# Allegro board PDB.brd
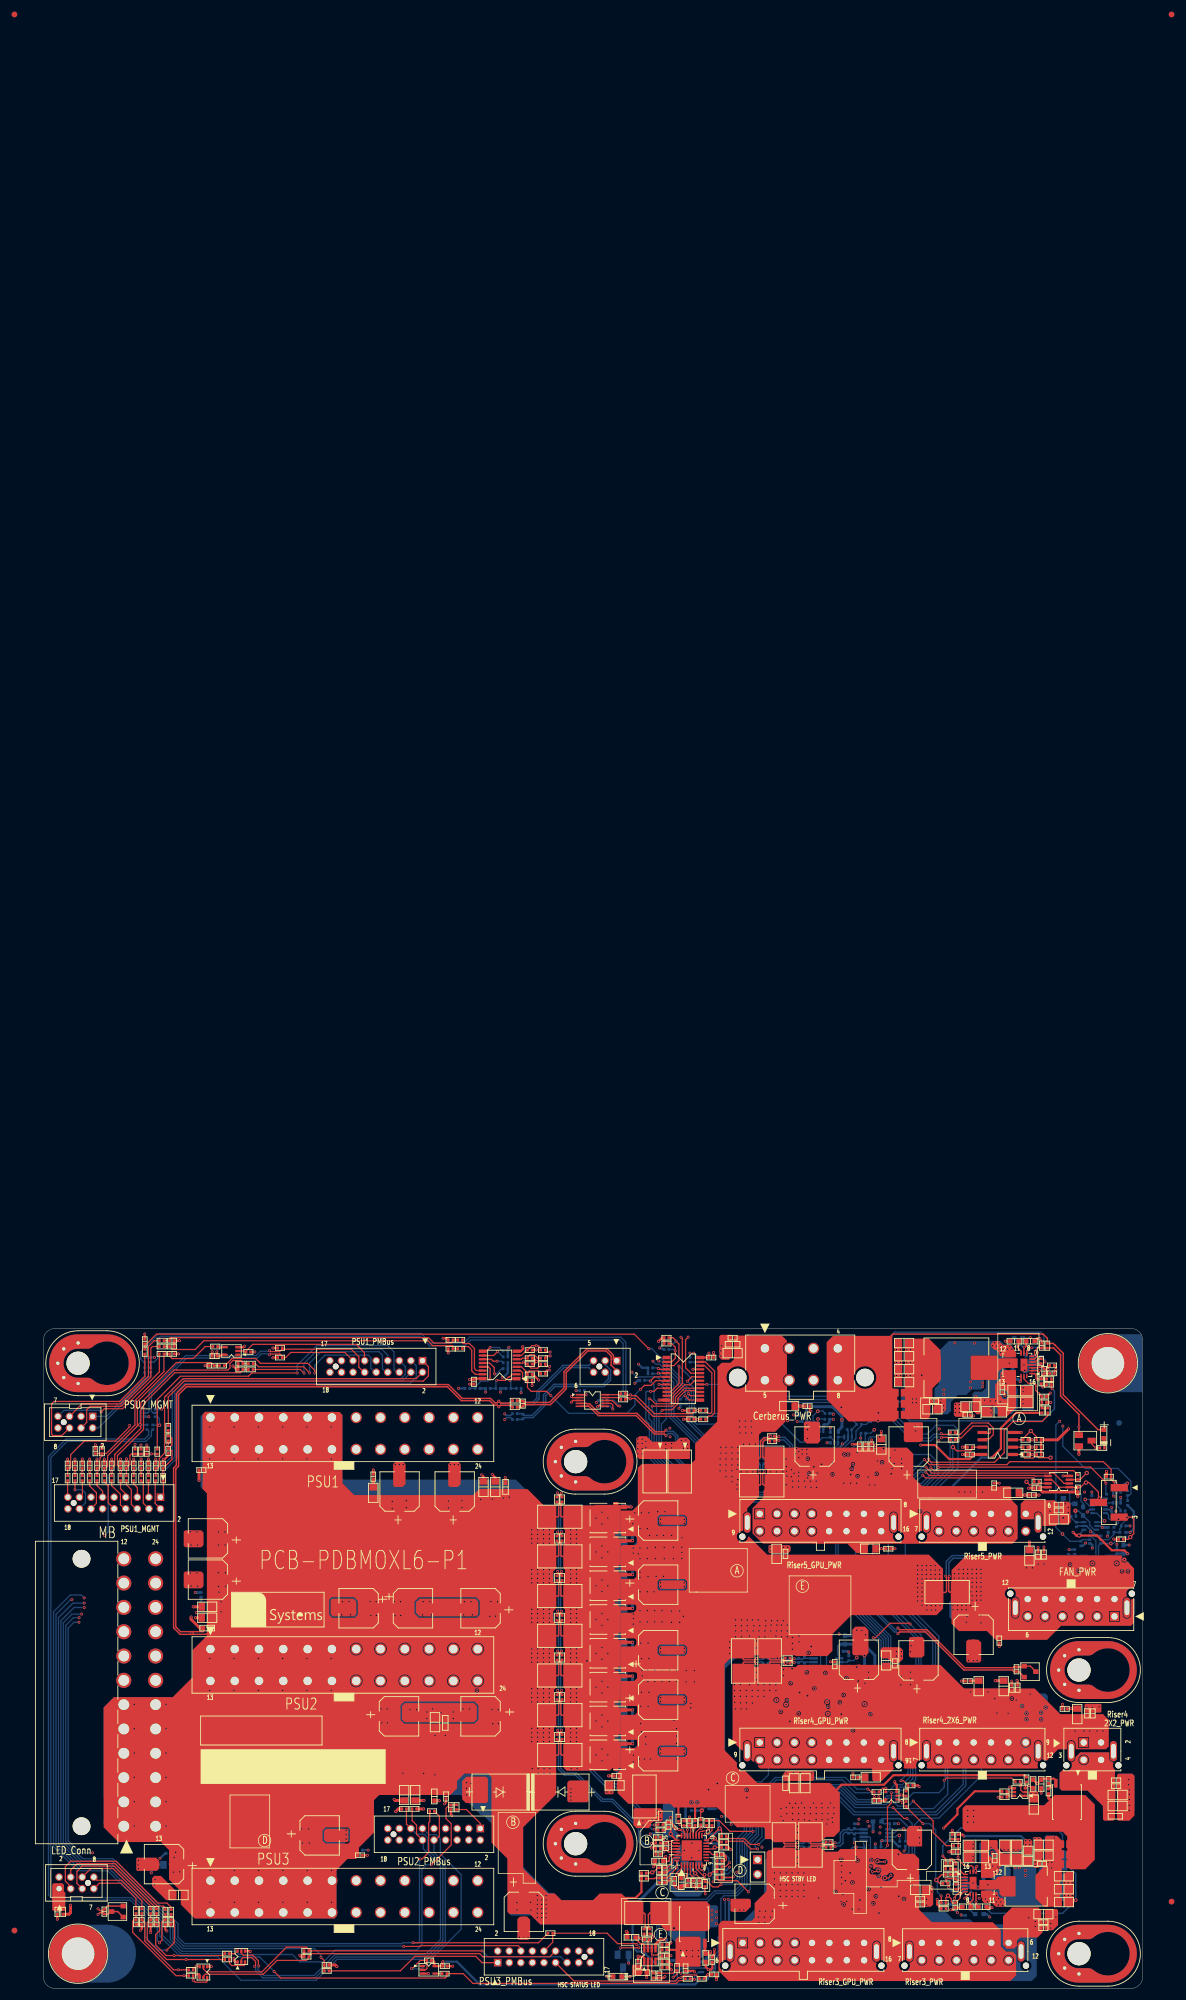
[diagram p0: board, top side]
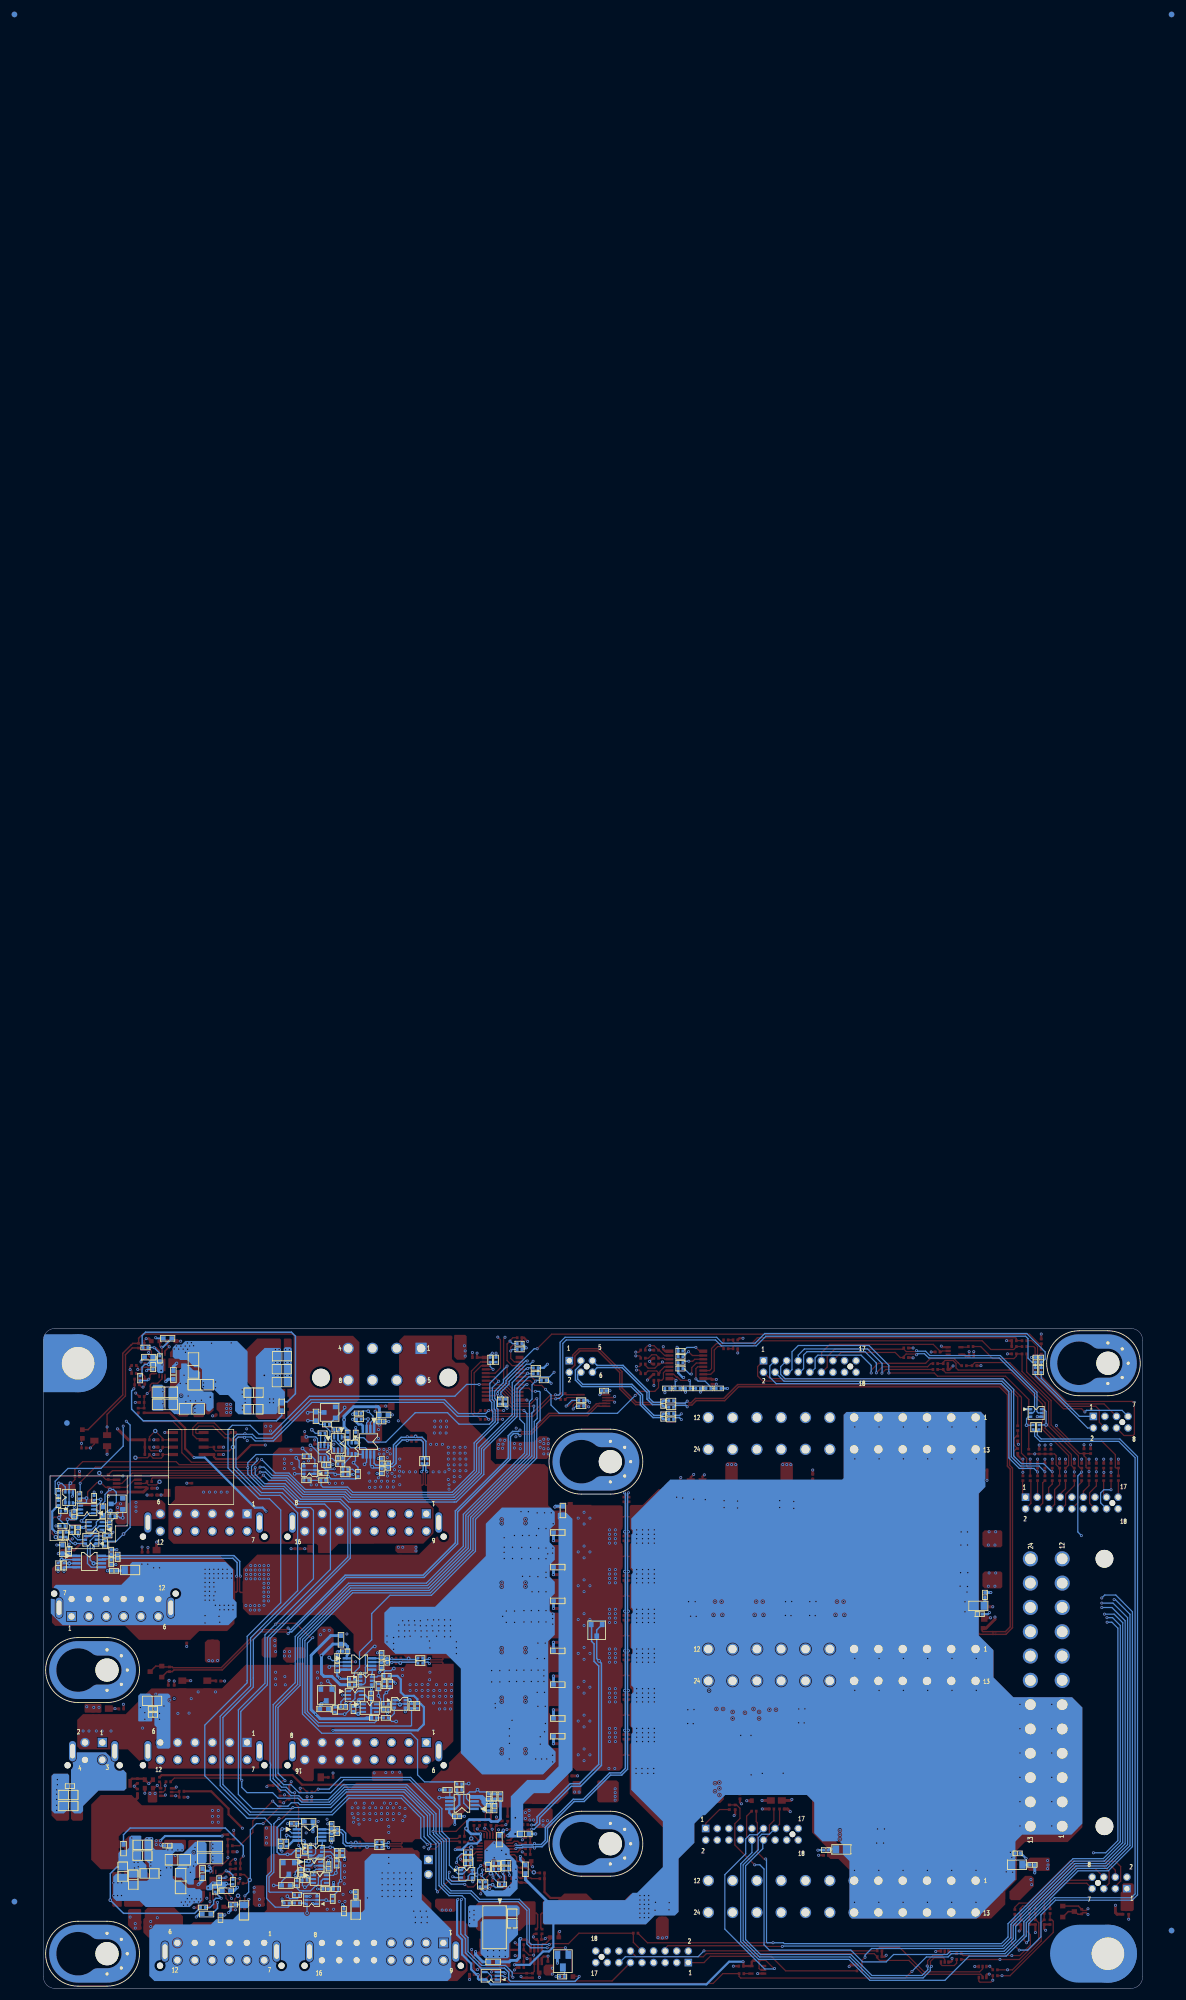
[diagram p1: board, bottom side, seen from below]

Outline 190 x 114 mm; copper layers: TOP, GND, VCC, VCC1, GND1, BOTTOM. Coordinates in mm from the lower left corner of the outline.
Outline path: 0,112 0,2 arc(0.59,0.59) 2,0 188,0 arc(189.41,0.59) 190,2 190,112 arc(189.93,112.52) 189.73,113 arc(189,113.73) 188,114 2,114 arc(0.59,113.41) 0,112

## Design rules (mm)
constraint set DEFAULT: min track width 0.216

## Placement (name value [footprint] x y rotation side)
C1  -  [EC_F80_H8]  61.57 85.84 90 top
C2  -  [EC_F80_H8]  71.09 85.84 90 top
C3  -  [EC_F80_H8]  20.85 21.48 180 top
C4  -  [EC_F80_H8]  83.06 13.22 270 top
C5  -  [C0805]  62.36 33.42 270 top
C6  -  [C0805]  76.07 86.63 90 top
C7  -  [C0805]  23.37 16.14 180 top
C8  -  [C0805]  28.32 64.02 180 top
C9  -  [C0805]  78.11 86.63 90 top
C10  -  [C0805]  67.69 45.99 90 top
C11  -  [C0805]  28.32 65.93 180 top
C12  -  [C0805]  64.26 33.42 270 top
C13  -  [C0603]  67.56 33.16 270 top
C14  -  [C0603]  69.47 45.86 90 top
C15  -  [C0603]  28.32 62.24 180 top
C16  -  [C0402]  144.02 32.4 180 top
C17  -  [C0603]  79.88 86.63 90 top
C18  -  [EC_F80_H8]  75.56 65.67 180 top
C19  -  [EC_F80_H8]  106.27 40.97 0 top
C20  -  [EC_F80_H8]  160.78 61.1 270 top
C21  -  [C0805]  131.7 35.45 90 top
C22  -  [C0805]  170.43 74.77 90 top
C23  -  [C0402]  99.06 36.72 180 top
C24  -  [C0402]  172.94 74.95 90 top
C25  -  [C0402]  17.53 111.77 90 top
C26  -  [C0402]  29.59 109.23 180 top
C27  -  [C0402]  17.88 92.73 90 top
C28  -  [C0402]  171.68 86.42 180 top
C29  -  [C0402]  29.08 107.58 180 top
C30  -  [C0402]  48.97 4.05 0 top
C31  -  [C0402]  70.42 31.3 270 top
C32  -  [C0402]  21.59 92.85 270 top
C33  -  [C0402]  74.42 104.79 270 top
C34  -  [C0402]  115.44 108.98 0 top
C35  -  [C0402]  93.09 103.27 180 bottom
C36  -  [C0402]  160.12 92.23 180 top
C37  -  [C0402]  168.2 55.13 270 top
C38  -  [C0402]  10.54 13.27 90 top
C39  -  [C0402]  131.55 57.57 90 bottom
C40  -  [C0402]  140.18 28.03 90 bottom
C41  -  [C0402]  131.55 55.79 270 bottom
C42  -  [C0402]  140.18 26.25 270 bottom
C43  -  [C0402]  146.69 28.46 180 bottom
C44  -  [C0402]  137.82 58.23 180 bottom
C45  -  [C0402]  149 25.01 270 bottom
C46  -  [C0402]  139.22 57.04 90 bottom
C47  -  [C0402]  145.47 20.06 270 bottom
C48  -  [C0402]  138.18 48.66 180 bottom
C49  -  [C0402]  131.5 91.12 90 bottom
C50  -  [C0402]  178.26 75.4 90 bottom
C51  -  [C0402]  131.5 89.35 270 bottom
C52  -  [C0402]  178.26 73.62 270 bottom
C53  -  [C0402]  131.57 97.93 0 bottom
C54  -  [C0402]  185.55 75.48 270 bottom
C55  -  [C0402]  135.48 99.33 0 bottom
C56  -  [C0402]  187.45 73.07 270 bottom
C57  -  [C0402]  139.32 96.53 180 bottom
C58  -  [C0402]  178.56 80.13 270 bottom
C59  -  [C0402]  113.03 33.16 270 bottom
C60  -  [C0402]  112.01 31.13 90 bottom
C61  -  [C0402]  118.49 29.73 180 bottom
C62  -  [C0402]  2.41 13.22 270 top
C63  -  [C0402]  128.27 75.07 90 top
C64  -  [C0402]  171.92 74.95 90 top
C65  -  [EC_F80_H8]  150.11 23.94 90 top
C66  -  [C0805]  151.54 17.03 0 top
C67  -  [C0402]  151.54 14.49 0 top
C68  -  [C0402]  151.54 15.51 0 top
C69  -  [EC_F80_H8]  133.3 93.61 90 top
C70  -  [C0805]  144.83 93.94 90 top
C71  -  [C0402]  142.11 93.61 90 top
C72  -  [EC_F80_H8]  151.26 56.66 90 top
C73  -  [C0402]  143.13 93.61 90 top
C74  -  [C0805]  145.67 56.66 90 top
C75  -  [C0402]  167.39 51.96 90 top
C76  -  [C0402]  147.19 56.15 90 top
C77  -  [EC_F80_H8]  61.47 47 0 top
C78  -  [EC_F80_H8]  28.45 70.63 180 top
C79  -  [EC_F80_H8]  47.75 26.43 0 top
C80  -  [EC_F80_H8]  75.56 47 180 top
C81  -  [EC_F80_H8]  28.45 77.74 180 top
C82  -  [EC_F80_H8]  63.88 65.67 0 top
C83  -  [EC_F80_H8]  54.48 65.67 180 top
C84  -  [EC_F80_H8]  122.94 14.62 180 top
C85  -  [C0402]  180.38 47.51 90 top
C86  -  [C0402]  181.39 47.51 90 top
C87  -  [EC_F80_H8]  149.56 93.61 90 top
C88  -  [C0805]  165.99 52.21 90 top
C89  -  [EC_F80_H8]  140.97 56.78 90 top
C90  -  [C0402]  185.42 34.94 0 bottom
C91  -  [C0402]  185.42 34.94 0 top
C92  -  [C0805]  185.67 33.42 0 bottom
C93  -  [C0402]  130.56 56.66 270 bottom
C94  -  [C0402]  139.19 27.19 270 bottom
C95  -  [C0402]  130.4 90.31 270 bottom
C96  -  [C0402]  177.16 74.56 270 bottom
C97  -  [C0402]  140.72 21.1 90 bottom
C98  -  [C0402]  133.35 50.56 90 bottom
C99  -  [C0402]  141.22 17.16 180 bottom
C100  -  [C0402]  130.81 48.15 180 bottom
C101  -  [C0402]  138.68 91.58 180 bottom
C102  -  [C0402]  184.02 79.24 270 bottom
C103  -  [C0402]  141.1 90.44 180 bottom
C104  -  [C0402]  184.66 81.9 270 bottom
C105  -  [C0402]  115.62 4.97 90 top
C106  -  [C0402]  102.79 4.26 270 top
C107  -  [C0402]  107.37 5.65 0 top
C108  -  [C0603]  101.65 8.83 180 top
C109  -  [C0402]  106.48 2.22 270 top
C110  -  [C0402]  104.32 8.45 0 top
C111  -  [C0402]  82.88 101.03 270 top
C112  -  [C0402]  82.88 98.8 90 bottom
C113  -  [C0402]  82.88 101.03 270 bottom
C114  -  [C0402]  69.39 3.85 0 top
C115  -  [C0402]  115.95 2.43 0 top
C116  -  [C0402]  8.99 92.8 90 top
C117  -  [C0805]  172.85 12.84 0 top
C118  -  [C0805]  171.2 49.67 0 bottom
C119  -  [C0402]  172.85 10.43 0 top
C120  -  [C0805]  175.51 81.04 0 top
C121  -  [C0402]  171.07 47.26 0 bottom
C122  -  [C0402]  172.85 11.44 0 top
C123  -  [C0402]  175.51 83.58 0 top
C124  -  [C0402]  171.07 48.27 0 bottom
C125  -  [C0402]  175.51 82.56 0 top
C126  -  [C0805]  108.97 12.08 90 bottom
C127  -  [C0402]  111 3.44 270 top
C128  -  [C0402]  4.19 90.29 90 top
C129  -  [C0402]  6.73 90.29 90 top
C130  -  [C0402]  9.27 90.29 90 top
C131  -  [C0402]  13.34 90.29 90 top
C132  -  [C0402]  15.62 90.29 90 top
C133  -  [C0402]  22.23 109.62 0 top
C134  -  [C0402]  18.16 90.29 90 top
C135  -  [C0402]  22.23 111.9 0 top
C136  -  [C0402]  20.7 90.29 90 top
C137  -  [C0402]  17.53 108.6 90 bottom
C138  -  [C0402]  5.46 90.29 90 top
C139  -  [C0402]  8 90.29 90 top
C140  -  [C0402]  22.23 110.89 0 top
C141  -  [C0402]  10.54 90.29 90 top
C142  -  [C0402]  18.54 108.6 90 bottom
C143  -  [C0402]  11.81 90.29 90 top
C144  -  [C0402]  14.35 90.29 90 top
C145  -  [C0402]  16.89 90.29 90 top
C146  -  [C0402]  19.43 90.29 90 top
C147  -  [C0402]  22.1 11.44 270 top
C148  -  [C0402]  19.56 11.44 270 top
C149  -  [C0402]  16 11.44 270 top
C150  -  [C0402]  17.02 11.44 270 top
C151  -  [C0402]  18.54 11.44 270 top
C152  -  [C0402]  21.08 11.44 270 top
C153  -  [C0402]  27.3 89.55 180 top
C154  -  [C0402]  21.62 23.33 180 bottom
C155  -  [C0402]  54.74 23 0 top
C156  -  [C0402]  28.17 64.66 180 bottom
C157  -  [C0402]  69.6 33.16 270 top
C158  -  [C0402]  119.13 112.41 180 top
C159  -  [C0402]  165.23 60.09 270 top
C160  -  [C0402]  159.38 12.21 90 bottom
C161  -  [C0402]  168.4 51.96 90 top
C162  -  [C0402]  164.34 86.88 90 top
C163  -  [C0402]  138.05 13.35 90 bottom
C164  -  [C0402]  136.78 56.02 90 top
C165  -  [C0402]  141.1 93.61 90 top
C166  -  [C0402]  57.02 88.41 90 top
C167  -  [C0402]  136.02 16.27 90 bottom
C168  -  [C0402]  19.05 21.35 180 bottom
C170  -  [C0402]  27.25 67.99 90 bottom
C171  -  [C0402]  140.34 36.46 180 top
C172  -  [C0402]  54.74 23.89 0 bottom
C174  -  [C0402]  177.8 72.15 0 bottom
C175  -  [C0402]  146.05 75.96 0 top
C176  -  [C0402]  132.08 100.6 0 top
C178  -  [C0402]  176.53 48.27 180 top
C191  -  [C0402]  157.23 14.49 0 bottom
C192  -  [C0402]  159.77 53.1 180 top
C193  -  [C0402]  170.81 85.23 0 top
CON1  -  [HEADER1X3S_P2-54H9-65XA]  184.15 83.96 0 top
D1  -  [LED0603]  99.21 2.05 0 top
D2  -  [SOT23]  147.57 20.72 270 bottom
D3  -  [SOT23]  141.1 50.69 270 bottom
D4  -  [SOT23]  140.51 99.51 0 bottom
D5  -  [SOT23]  177.29 83.71 0 bottom
D6  -  [LED0603]  183.26 95.77 270 top
D7  -  [POWERDI5_5-37X3-96]  105.66 89.3 270 top
D8  -  [POWERDI5_5-37X3-96]  112.01 10.56 270 bottom
D9  -  [POWERDI5_5-37X3-96]  109.98 89.3 270 top
D10  -  [POWERDI5_5-37X3-96]  103.89 33.16 90 top
D11  -  [D_SMCJ_6-85X5-9H2-62]  78.87 33.92 0 top
J1  -  [PWR2X12D_P4-2W5-5H12-8]  28.87 98.62 90 top
J2  -  [PWR2X12D2NH_P4-2W5-5H10_RA]  13.9 28.02 180 top
J3  -  [PWR2X12D_P4-2W5-5H12-8]  28.87 58.62 90 top
J4  -  [PWR2X12D_P4-2W5-5H12-8]  28.87 18.62 90 top
J5  -  [HEADER2X9D1NH_P2W2H6-4]  65.53 108.44 180 top
J6  -  [HEADER2X9D1NH_P2W2H6-4]  75.52 27.63 180 top
J7  -  [HEADER2X9D1NH_P2W2H6-4]  78.53 4.46 0 top
J8  -  [HEADER2X9D1NH_P2W2H6-4]  20.24 84.86 180 top
J9  -  [HEADER2X4D1NH_P2W2H6-4]  8.52 98.82 180 top
J10  -  [HEADER2X4D1NH_P2W2H6-4]  2.72 17.23 0 top
J11  -  [PWR2X6D2D2NH_P3W3H10-15]  185.13 64.26 270 top
J12  -  [PWR2X4D2NH_P4-2W5-5H12-8]  124.71 110.57 90 top
J13  -  [PWR2X8D2D2NH_P3W3H10-15]  120.86 7.86 90 top
J14  -  [PWR2X8D2D2NH_P3W3H10-15]  123.81 42.49 90 top
J15  -  [PWR2X8D2D2NH_P3W3H10-15]  123.81 81.98 90 top
J16  -  [PWR2X6D2D2NH_P3W3H10-15]  151.84 7.87 90 top
J17  -  [PWR2X6D2D2NH_P3W3H10-15]  154.79 42.49 90 top
J18  -  [PWR2X6D2D2NH_P3W3H10-15]  154.79 81.99 90 top
J19  -  [PWR2X2D2D2NH_P3W3H10-15]  179.81 42.49 90 top
J20  -  [HEADER1X2_P2-54H8-6]  123.44 22.24 0 top
J21  -  [HEADER2X3D1NH_P2W2H6-4]  99.1 108.44 180 top
L1  -  [B0402]  20.7 88.13 270 top
L2  -  [B0402]  18.16 88.13 270 top
L3  -  [B0402]  15.62 88.13 270 top
L4  -  [B0402]  13.34 88.13 270 top
L5  -  [B0402]  9.27 88.13 270 top
L6  -  [B0402]  6.73 88.13 270 top
L7  -  [B0402]  4.19 88.13 270 top
L8  -  [B0402]  17.53 106.82 270 bottom
L9  -  [B0402]  20.45 111.9 180 top
L10  -  [B0402]  20.45 109.62 180 top
L11  -  [B0402]  19.43 88.13 90 top
L12  -  [B0402]  16.89 88.13 90 top
L13  -  [B0402]  14.35 88.13 90 top
L14  -  [B0402]  11.81 88.13 90 top
L15  -  [B0402]  10.54 88.13 90 top
L16  -  [B0402]  8 88.13 90 top
L17  -  [B0402]  5.46 88.13 90 top
L18  -  [B0402]  18.54 106.82 90 bottom
L19  -  [B0402]  20.45 110.89 0 top
L20  -  [B0402]  17.53 110 90 top
L21  -  [B0402]  22.1 13.22 90 top
L22  -  [B0402]  19.56 13.35 90 top
L23  -  [B0402]  16 13.35 90 top
L24  -  [B0402]  21.08 13.22 270 top
L25  -  [B0402]  18.54 13.35 270 top
L26  -  [B0402]  17.02 13.35 270 top
L33  -  [B0402]  3.43 13.22 270 top
ME1  -  [ZT_LOG_6X16_Z1]  32.51 62.44 0 top
ME2  -  [LABEL20X4_SST21X5]  27.18 42.05 0 top
ME3  -  [LABEL_32X6_FULL]  27.18 35.32 0 top
MH1  -  [GND_C10D4_6-5B10_OB5]  6 108 90 top
MH2  -  [GND_C10D4_6-5B10_OB5]  92 25 90 top
MH3  -  [GND_C10D4_6-5B10_OB5]  92 91 90 top
MH4  -  [GND_C10D4_6-5B10_OB5]  179 55 90 top
MH5  -  [GND_C10D4_6-5B10_OB5]  179 6 90 top
MH6  -  [HOLE_C10D5-6B10_NPB_H11_STANDOFF]  184 108 0 top
MH7  -  [HOLE_C10D5-6B10_NPB_H11_STANDOFF]  6 6 0 top
NOREF  -  [unnamed]  195 341 0 top
NOREF#2  -  [unnamed]  195 15 0 top
NOREF#3  -  [unnamed]  -5 10 0 top
NOREF#4  -  [#2]  -20.95 -94.35 0 top
NOREF#5  -  [unnamed]  -5 341 0 top
NOREF#6  -  [unnamed]  -5 341 180 bottom
NOREF#7  -  [unnamed]  195 341 180 bottom
NOREF#8  -  [unnamed]  195 15 180 bottom
NOREF#9  -  [unnamed]  -5 10 180 bottom
NOREF#10  -  [unnamed]  185.93 97.68 180 bottom
PC28  -  [C0402]  173.74 35.83 90 top
PC29  -  [C0805]  171.2 31.76 90 top
PC30  -  [C0805]  185.67 31.51 0 top
PC31  -  [C0805]  185.67 31.51 0 bottom
PC32  -  [C0805]  185.67 33.42 0 top
PC33  -  [C0402]  185.42 35.96 0 top
PC34  -  [C0603]  172.47 35.32 270 top
PC101  -  [EC_F80_H8]  106.27 49.89 0 top
PC102  -  [EC_F80_H8]  106.27 58.42 0 top
PC103  -  [EC_F80_H8]  106.27 80.82 0 top
PC104  -  [C0805]  98.73 35.07 180 top
PC105  -  [C0805]  119.13 109.74 180 top
PC106  -  [EC_F80_H8]  106.27 69.75 0 top
PC107  -  [C0805]  126.75 75.07 90 top
PC108  -  [C0805]  129.79 35.45 90 top
PC109  -  [C0603]  110.26 18.35 270 top
PC819  -  [C0402]  157.7 23.61 180 top
PC820  -  [C0402]  157.62 14.37 270 top
PC822  -  [C0603]  162.34 14.11 0 top
PC823  -  [C0402]  159.61 18.66 270 bottom
PC824  -  [C0603]  159.57 14.11 180 top
PC825  -  [C0402]  164.42 22.51 90 top
PC827  -  [C1206]  161.17 22.63 180 top
PC828  -  [C0603]  162.48 19.95 270 bottom
PC829  -  [C0402]  157.71 19.28 90 top
PC830  -  [C1206]  161.17 24.7 180 top
PC831  -  [C0402]  156.34 19.67 0 top
PC832  -  [C1206]  166.2 23.45 90 top
PC833  -  [C1206]  168.26 23.45 90 top
PC834  -  [C0805]  176.29 20.18 270 bottom
PC835  -  [C0402]  172.61 21.55 180 top
PC836  -  [C1206]  166.28 18.55 270 bottom
PC837  -  [C0805]  176.41 14.92 0 top
PC838  -  [C0805]  176.4 19.39 0 top
PC840  -  [C0805]  174.46 18.79 270 bottom
PC841  -  [C0805]  172.88 24.8 180 top
PC842  -  [C0402]  156.35 21.62 180 top
PC843  -  [C1206]  161.17 22.44 180 bottom
PC844  -  [C0805]  172.86 24.8 180 bottom
PC845  -  [C0805]  176.4 17.15 0 top
PC846  -  [C1206]  166.76 22.23 0 bottom
PC847  -  [C0805]  171.65 19.87 180 bottom
PC848  -  [C0805]  172.88 22.95 180 top
PC849  -  [C1206]  161.2 24.52 180 bottom
PC850  -  [C0805]  172.87 22.95 180 bottom
PC851  -  [C0402]  168.56 24.67 180 bottom
PC1010  -  [C0402]  112.39 18.2 270 top
PC1011  -  [C0402]  116.84 23.13 0 top
PC1012  -  [C0402]  109.04 18.56 270 top
PC1013  -  [C0402]  107.39 18.68 270 top
PC1014  -  [C0402]  111.43 18.2 270 top
PC1015  -  [C0402]  107.39 20.44 270 top
PC1016  -  [C0402]  113.41 18.18 270 top
PC1017  -  [C0603]  106.43 21.99 180 top
PC1018  -  [C0402]  106.25 23.15 0 top
PC1019  -  [C0402]  107.62 24.63 90 top
PC1020  -  [C0402]  106.25 26.13 0 top
PC1021  -  [C0402]  108.05 28.28 270 top
PC1022  -  [C0603]  106.81 26.68 180 bottom
PC1023  -  [C0402]  111.68 28.54 90 top
PC1024  -  [C0603]  119.13 111.27 180 top
PC1819  -  [C0402]  172.97 102.25 0 top
PC1820  -  [C0402]  172.57 111.04 90 top
PC1822  -  [C0603]  167.84 111.81 180 top
PC1823  -  [C0402]  171.02 107.33 90 bottom
PC1824  -  [C0603]  170.61 111.81 0 top
PC1825  -  [C0402]  165.76 103.41 270 top
PC1827  -  [C1206]  168.88 103.28 0 top
PC1828  -  [C0603]  167.54 105.97 90 bottom
PC1829  -  [C0402]  172.99 106.64 270 top
PC1830  -  [C1206]  168.88 101.22 0 top
PC1831  -  [C0402]  174.35 106.25 180 top
PC1832  -  [C1206]  168.99 100.89 0 bottom
PC1833  -  [C1206]  169.01 102.97 0 bottom
PC1834  -  [C0805]  148.79 104.75 180 bottom
PC1835  -  [C0402]  153.94 101.45 0 top
PC1836  -  [C1206]  164.06 107.62 90 bottom
PC1837  -  [C0805]  148.77 109.22 180 top
PC1838  -  [C0805]  148.78 104.75 180 top
PC1840  -  [C0805]  148.78 106.99 180 top
PC1841  -  [C0805]  148.77 111.48 180 top
PC1842  -  [C0402]  173.83 104.29 0 top
PC1843  -  [C1206]  164.31 100.13 180 bottom
PC1844  -  [C0805]  148.77 109.22 180 bottom
PC1845  -  [C0805]  148.79 106.99 180 bottom
PC1846  -  [C1206]  164.31 99.62 180 top
PC1847  -  [C0805]  153.67 102.92 0 bottom
PC1848  -  [C0805]  153.67 100.05 0 top
PC1849  -  [C1206]  162.81 104.29 180 bottom
PC1850  -  [C0805]  153.68 100.05 0 bottom
PC1851  -  [C0402]  159.74 99.09 0 top
PD1  -  [D_SMCJ_6-85X5-9H2-62]  89.53 33.92 180 top
PL26  -  [IND_PCMC063T]  169.86 17.64 0 top
PL28  -  [B2012]  170.22 22.9 90 top
PL126  -  [IND_PCMB104TXA]  157.81 107.21 180 top
PL128  -  [B2012]  160.24 100.51 180 top
PQ2  -  [SOT363]  168.78 33.92 180 top
PQ3  -  [SOT1023]  176.91 32.02 270 top
PQ101  -  [DFN5_P1-27_4-9X5-9_Z1]  97.55 46.21 270 top
PQ102  -  [DFN5_P1-27_4-9X5-9_Z1]  97.55 40.36 270 top
PQ103  -  [DFN5_P1-27_4-9X5-9_Z1]  97.55 81.26 270 top
PQ104  -  [DFN5_P1-27_4-9X5-9_Z1]  97.55 69.57 270 top
PQ105  -  [DFN5_P1-27_4-9X5-9_Z1]  97.55 75.42 270 top
PQ106  -  [DFN5_P1-27_4-9X5-9_Z1]  97.55 63.73 270 top
PQ107  -  [DFN5_P1-27_4-9X5-9_Z1]  97.55 52.05 270 top
PQ108  -  [DFN5_P1-27_4-9X5-9_Z1]  97.55 57.89 270 top
PQ109  -  [SOT23]  94.36 61.86 270 bottom
PR22  -  [R0402]  168.4 35.7 0 top
PR23  -  [R0402]  166.12 34.05 0 top
PR24  -  [R0402]  166.12 33.03 180 top
PR25  -  [R0402]  169.93 36.08 270 top
PR26  -  [R0603]  171.07 35.32 90 top
PR27  -  [R0402]  173.74 34.05 90 top
PR101  -  [R0603]  101.09 66.94 180 bottom
PR102  -  [R0603]  101.09 46.62 180 bottom
PR103  -  [R0603]  101.09 43.58 180 bottom
PR104  -  [R0603]  100.2 82.56 270 bottom
PR105  -  [R0603]  101.09 72.79 180 bottom
PR106  -  [R0603]  101.09 78.75 180 bottom
PR107  -  [R0603]  101.09 58.31 180 bottom
PR108  -  [R0402]  110.72 17.97 0 bottom
PR109  -  [R0402]  113.13 21 90 bottom
PR702  -  [R0402]  157.73 24.65 0 top
PR704  -  [R0402]  155.6 14.79 0 top
PR705  -  [R0402]  155.6 13.78 0 top
PR706  -  [R0402]  157.72 17.55 90 top
PR707  -  [R0603]  158.4 16.87 180 bottom
PR708  -  [R0603]  161.8 12.84 180 bottom
PR710  -  [R0402]  155.91 18.15 180 top
PR711  -  [R0402]  160.31 17.08 270 bottom
PR712  -  [R0402]  157.25 18.4 90 bottom
PR714  -  [R0402]  162.43 13.98 0 bottom
PR716  -  [R0402]  157.71 21.03 90 top
PR717  -  [R0402]  156.35 20.66 180 top
PR719  -  [R0603]  176.15 24.14 270 bottom
PR1010  -  [R0402]  116.89 22.01 0 top
PR1011  -  [R0402]  116.89 21.05 180 top
PR1012  -  [R0402]  110.01 20.72 180 bottom
PR1013  -  [R0402]  110.01 21.71 0 bottom
PR1014  -  [R0402]  116.87 20.16 180 top
PR1015  -  [R0402]  88.77 64.02 270 top
PR1016  -  [R0402]  88.77 70.88 270 top
PR1017  -  [R0402]  88.77 77.74 270 top
PR1018  -  [R0402]  88.77 84.47 270 top
PR1019  -  [R0402]  88.77 57.16 270 top
PR1020  -  [R0402]  88.77 50.31 270 top
PR1027  -  [R0402]  89.66 50.31 270 top
PR1028  -  [R0402]  89.66 57.16 270 top
PR1029  -  [R0402]  89.66 64.02 270 top
PR1030  -  [R0402]  89.66 70.88 270 top
PR1031  -  [R0402]  89.66 77.74 270 top
PR1032  -  [R0402]  89.66 84.47 270 top
PR1033  -  [R0402]  106.43 18.68 270 top
PR1034  -  [R0402]  103.78 18.96 0 top
PR1035  -  [R0402]  111.76 20.61 0 bottom
PR1036  -  [R0402]  111.76 21.6 180 bottom
PR1037  -  [R0402]  106.43 20.44 270 top
PR1038  -  [R0402]  103.78 19.95 0 top
PR1039  -  [R0603]  106.68 20.59 90 bottom
PR1040  -  [R0603]  111.18 25.69 90 bottom
PR1041  -  [R0402]  106.25 24.14 0 top
PR1042  -  [R0402]  106.25 25.14 0 top
PR1043  -  [R0402]  117.63 26.28 0 top
PR1044  -  [R0402]  117.63 25.29 0 top
PR1045  -  [R0402]  112.65 28.56 270 top
PR1046  -  [R0402]  106.68 28.28 180 top
PR1047  -  [R0402]  106.68 27.32 180 top
PR1048  -  [R0402]  109.75 29.3 270 top
PR1049  -  [R0603]  101.09 52.47 180 bottom
PR1050  -  [R0402]  110.72 28.54 90 top
PR1705  -  [R0402]  173.53 111.03 270 top
PR1706  -  [R0402]  172.46 108.36 270 top
PR1707  -  [R0603]  171.78 109.04 0 bottom
PR1708  -  [R0603]  168.53 112.31 180 bottom
PR1710  -  [R0402]  174.34 107.62 0 top
PR1711  -  [R0402]  169.87 108.83 90 bottom
PR1712  -  [R0402]  173.28 105.4 270 bottom
PR1714  -  [R0402]  172.36 110.72 0 bottom
PR1716  -  [R0402]  172.48 104.88 270 top
PR1717  -  [R0402]  173.83 105.26 0 top
PR1719  -  [R0603]  148.79 100.56 90 bottom
PR10152  -  [R0402]  115.57 28.56 90 top
PR10153  -  [R0402]  117.63 24.32 180 top
PR10154  -  [R0402]  114.35 18.02 90 top
PSHORT5  -  [SHORT0805]  176.4 23.13 0 top
PSHORT6  -  [SHORT0805]  176.4 21.48 0 top
PSHORT7  -  [SHORT0805]  176.4 24.91 0 top
PSHORT15  -  [SHORT0805]  148.21 99.09 180 top
PSHORT61  -  [SHORT0805]  148.21 100.99 180 top
PSHORT71  -  [SHORT0805]  148.21 102.9 180 top
PU10  -  [R2512_SMD126X146]  132.59 24.78 270 top
PU11  -  [R2512_SMD126X146]  128.02 24.78 270 top
PU12  -  [LFCSP_WQ32_TH]  112.06 23.84 90 top
PU13  -  [R2512_SMD126X146]  120.95 56.57 270 top
PU14  -  [R2512_SMD126X146]  125.52 56.57 270 top
PU15  -  [R2512_SMD126X146]  124.17 91.66 0 top
PU16  -  [R2512_SMD126X146]  124.17 86.93 0 top
PU17  -  [R2512XA_Z1]  156.21 68.47 0 top
PU18  -  [R2512XA_Z1]  89.26 81.49 0 top
PU19  -  [R2512XA_Z1]  89.26 74.63 0 top
PU20  -  [R2512XA_Z1]  89.26 67.77 0 top
PU21  -  [R2512XA_Z1]  89.26 60.91 0 top
PU22  -  [R2512XA_Z1]  89.26 54.06 0 top
PU23  -  [R2512XA_Z1]  89.26 47.2 0 top
PU33  -  [PQFN17_IR3899]  161.84 18.2 270 top
PU113  -  [PQFN17_IR3899]  168.34 107.71 90 top
Q1  -  [SOT363]  144.02 89.55 0 bottom
Q2  -  [SOT363]  185.55 84.83 90 bottom
Q3  -  [SOT23_GDS]  100.2 4.71 270 bottom
Q4  -  [SOT23_GDS]  180.09 94.63 0 top
Q5  -  [SOT1023]  112.45 11.24 90 top
Q10  -  [SOT23]  170.54 54.73 0 top
Q11  -  [SOT23]  12.8 13.28 180 top
Q13  -  [SOT363]  142.85 23.61 180 bottom
Q14  -  [SOT363]  134.21 53.15 180 bottom
Q15  -  [SOT363]  136.7 93.31 270 bottom
Q16  -  [SOT363]  181.79 77.51 0 bottom
Q17  -  [SOT363]  143.64 15.25 0 bottom
Q18  -  [SOT363]  128.4 49.16 180 bottom
Q19  -  [SOT363]  116.81 19.8 180 bottom
Q20  -  [SOT363]  18.41 99.41 180 bottom
Q21  -  [SOT363]  34.21 5.5 90 top
Q22  -  [SOT363]  27.66 2.83 270 top
R1  -  [R0402]  144.53 87.77 0 bottom
R2  -  [R0402]  141.6 89.04 0 bottom
R3  -  [R0402]  187.4 85.56 90 bottom
R4  -  [R0402]  186.59 82.49 180 bottom
R5  -  [R0402]  144.48 91.91 0 bottom
R6  -  [R0402]  183.77 84.98 90 bottom
R7  -  [R0402]  147.96 14.75 180 bottom
R8  -  [R0402]  125.35 48.78 270 bottom
R9  -  [R0402]  141.6 87.77 0 bottom
R10  -  [R0402]  187.4 83.86 90 bottom
R11  -  [R0402]  113.59 17.97 90 bottom
R12  -  [R0402]  114.55 17.97 270 bottom
R13  -  [R0402]  116.87 19.17 0 top
R14  -  [R0402]  114.6 28.56 90 top
R15  -  [R0402]  173.61 99.84 90 top
R16  -  [R0402]  149.1 31.89 90 top
R17  -  [R0402]  144.78 24.02 90 bottom
R18  -  [R0402]  136.65 53.48 0 bottom
R19  -  [R0402]  136.02 95.65 90 bottom
R20  -  [R0402]  179.32 76.85 270 bottom
R21  -  [R0603]  144.15 28.84 180 bottom
R22  -  [R0603]  138.56 60.21 90 bottom
R23  -  [R0603]  131.19 99.07 180 bottom
R24  -  [R0603]  186.69 75.86 90 bottom
R25  -  [R0402]  132.84 46.75 180 bottom
R26  -  [R0402]  139.45 17.16 0 bottom
R27  -  [R0402]  130.05 52.59 90 bottom
R28  -  [R0402]  137.79 88.79 180 bottom
R29  -  [R0402]  186.69 79.9 0 bottom
R30  -  [R0402]  40.89 108.98 180 top
R31  -  [R0402]  62.36 31 180 top
R32  -  [R0402]  45.47 6.49 180 top
R33  -  [R0402]  40.89 110.63 180 top
R34  -  [R0402]  64.14 31 0 top
R35  -  [R0402]  45.47 5.48 180 top
R36  -  [R0402]  138.3 23.38 90 bottom
R37  -  [R0402]  130.68 53.99 0 bottom
R38  -  [R0402]  135.61 88.84 90 bottom
R39  -  [R0402]  187.07 78.37 270 bottom
R40  -  [R0603]  148.08 17.79 180 bottom
R41  -  [R0603]  141.48 48.27 180 bottom
R42  -  [R0603]  142.88 98.82 270 bottom
R43  -  [R0603]  179.71 82.44 270 bottom
R44  -  [R0402]  100.33 2.05 180 bottom
R45  -  [R0402]  183.01 93.36 0 top
R46  -  [R0402]  97.03 101.59 0 bottom
R47  -  [R0603]  103.56 2.73 0 top
R48  -  [R2512XA_Z1]  104.32 13.02 0 top
R49  -  [R0603]  112.27 4.59 0 bottom
R50  -  [R0603]  114.48 5.27 270 top
R51  -  [R0402]  35.84 106.92 0 top
R52  -  [R0402]  86.36 107.85 0 top
R53  -  [R0402]  86.36 110.27 0 top
R54  -  [R0402]  35.84 107.94 180 top
R55  -  [R0402]  86.36 106.2 180 top
R56  -  [R0402]  86.36 108.87 180 top
R57  -  [R0805]  178.69 47.39 90 top
R58  -  [R0402]  88.77 43.45 270 top
R59  -  [R0402]  184.15 88.41 0 top
R60  -  [R0402]  178.79 86.16 90 top
R61  -  [R0402]  186.26 77.59 180 top
R62  -  [R0402]  35.43 109.95 180 top
R63  -  [R0402]  66.67 4.84 180 top
R64  -  [R0402]  113.79 1.67 180 top
R65  -  [R0402]  19.68 92.72 270 top
R66  -  [R0402]  15.85 92.73 270 top
R67  -  [R0402]  16.86 92.73 270 top
R68  -  [R0402]  29.72 110.89 180 top
R69  -  [R0402]  30.86 107.58 0 top
R70  -  [R0402]  67.18 30.62 0 top
R71  -  [R0402]  87.63 9.54 0 top
R72  -  [R0402]  21.59 96.79 270 top
R73  -  [R0402]  71.44 31.3 90 top
R74  -  [R0402]  48.97 3.04 180 top
R75  -  [R0402]  171.68 87.56 180 top
R76  -  [R0402]  178.79 88.32 90 top
R77  -  [R0402]  73.28 103.65 0 bottom
R78  -  [R0402]  75.06 103.65 0 bottom
R79  -  [R0402]  107.7 111.39 0 bottom
R80  -  [R0402]  107.7 112.41 180 top
R81  -  [R0402]  78.61 103.65 180 bottom
R82  -  [R0402]  76.83 103.65 180 bottom
R83  -  [R0402]  107.7 110.38 0 bottom
R84  -  [R0402]  107.7 111.39 180 top
R85  -  [R0402]  80.39 103.65 0 bottom
R86  -  [R0402]  82.17 103.65 0 bottom
R87  -  [R0402]  112.78 108.6 270 bottom
R88  -  [R0402]  111.76 108.6 90 bottom
R89  -  [R0402]  72.03 110.5 0 top
R90  -  [R0402]  72.03 112.03 0 top
R91  -  [R0402]  114.05 98.31 0 top
R92  -  [R0402]  114.05 99.84 0 top
R93  -  [R0402]  84.07 106.07 180 top
R94  -  [R0402]  84.07 107.85 180 top
R95  -  [R0402]  84.07 108.87 180 top
R96  -  [R0402]  84.07 110.27 180 top
R97  -  [R0402]  79.88 110.12 180 bottom
R98  -  [R0402]  79.88 109.11 180 bottom
R99  -  [R0402]  79.88 108.09 180 bottom
R100  -  [R0402]  79.88 107.08 180 bottom
R101  -  [R0402]  34.06 107.94 0 top
R102  -  [R0402]  34.06 106.92 0 top
R103  -  [R0402]  70.38 110.5 0 top
R104  -  [R0402]  70.38 112.03 0 top
R105  -  [R0402]  112.01 98.31 0 top
R106  -  [R0402]  112.01 99.84 0 top
R107  -  [R0402]  104.9 107.2 0 bottom
R108  -  [R0402]  104.9 106.19 0 bottom
R109  -  [R0402]  84.07 105.06 180 top
R110  -  [R0402]  21.59 95.01 90 top
R111  -  [R0402]  110.11 101.36 90 bottom
R112  -  [R0402]  111.12 101.36 90 bottom
R113  -  [R0402]  157.2 96.04 0 top
R114  -  [R0402]  157.2 94.77 0 top
R115  -  [R0402]  100.2 102.76 180 top
R116  -  [R0402]  100.2 101.74 180 top
R117  -  [R0402]  160.12 93.5 180 top
R118  -  [R0402]  172.06 92.23 180 top
R119  -  [R0402]  169.77 92.23 0 top
R120  -  [R0402]  172.06 93.5 180 top
R121  -  [R0402]  169.77 93.5 0 top
R122  -  [R0402]  172.06 94.77 180 top
R123  -  [R0402]  169.77 94.77 0 top
R124  -  [R0402]  97.03 100.57 0 bottom
R125  -  [R0603]  128.27 35.45 90 top
R126  -  [R0402]  145.92 23.38 270 bottom
R127  -  [R0402]  148.01 24.98 270 bottom
R128  -  [R0402]  136.65 52.47 180 bottom
R129  -  [R0402]  139.22 55.31 270 bottom
R130  -  [R0402]  139.32 23.38 270 bottom
R131  -  [R0402]  131.06 52.59 270 bottom
R132  -  [R0402]  139.32 21.6 270 bottom
R133  -  [R0402]  132.08 52.21 270 bottom
R134  -  [R0402]  146.18 18.18 90 bottom
R135  -  [R0402]  139.57 48.15 90 bottom
R136  -  [R0402]  144.83 18.68 180 bottom
R137  -  [R0402]  136.4 48.27 90 bottom
R138  -  [R0603]  185.29 29.73 0 top
R139  -  [R0402]  89.66 43.45 270 top
R140  -  [R0402]  137.41 95.65 270 bottom
R141  -  [R0402]  135.48 98.31 0 bottom
R142  -  [R0402]  178.94 78.25 0 bottom
R143  -  [R0402]  186.44 73.07 270 bottom
R144  -  [R0402]  137.79 89.68 0 bottom
R145  -  [R0402]  186.06 78.37 90 bottom
R146  -  [R0402]  138.68 90.57 0 bottom
R147  -  [R0402]  185.04 79.24 90 bottom
R148  -  [R0402]  140.97 97.42 180 bottom
R149  -  [R0402]  178.05 81.55 180 bottom
R150  -  [R0402]  141.73 95.9 180 bottom
R151  -  [R0402]  181.23 84.72 90 bottom
R152  -  [R0402]  107.37 4.64 180 top
R153  -  [R0402]  107.37 3.62 0 top
R154  -  [R0402]  103.81 9.84 270 top
R155  -  [R0402]  104.83 9.84 270 top
R156  -  [R0402]  120.14 34.3 0 bottom
R157  -  [R0402]  116.59 23.51 180 bottom
R158  -  [R0402]  116.59 22.62 0 bottom
R159  -  [R0402]  146.18 14.75 180 bottom
R160  -  [R0402]  140 15.48 270 bottom
R161  -  [R0402]  126.36 48.78 90 bottom
R162  -  [R0402]  130.81 49.16 180 bottom
R163  -  [R0402]  116.59 21.6 0 bottom
R164  -  [R0402]  113.61 28.69 90 top
R165  -  [R0402]  111 33.16 90 bottom
R166  -  [R0402]  112.01 33.16 270 bottom
R167  -  [R0402]  113.03 31.13 90 bottom
R168  -  [R0402]  118.11 34.3 180 bottom
R169  -  [R0402]  118.11 35.32 0 bottom
R170  -  [R0402]  146.18 16.14 0 bottom
R171  -  [R0402]  109.52 3.49 270 top
R172  -  [R0402]  130.81 46.75 0 bottom
R173  -  [R0402]  105.46 2.22 270 top
R174  -  [R0402]  17.91 96.95 90 bottom
R175  -  [R0402]  31.75 6.01 0 top
R176  -  [R0402]  25.5 2.2 0 top
R177  -  [R0402]  18.92 96.95 270 bottom
R178  -  [R0402]  31.75 5 180 top
R179  -  [R0402]  25.5 3.22 180 top
R180  -  [R0402]  107.37 6.67 180 top
R181  -  [R0402]  107.37 7.56 0 top
R182  -  [R0402]  135.7 25.27 180 top
R183  -  [R0402]  149.1 33.67 270 top
R184  -  [R0402]  144.02 33.92 180 top
R185  -  [R0402]  103.5 105.04 0 bottom
R186  -  [R0402]  69.34 2.55 0 top
R187  -  [R0402]  111.38 1.67 180 top
R188  -  [R0402]  10.13 92.8 270 top
R189  -  [R2512XA_Z1]  89.26 40.34 0 top
R191  -  [R0402]  81.48 101.54 180 top
R192  -  [R0402]  81.48 100.4 180 top
R193  -  [R0402]  81.48 98.29 180 bottom
R194  -  [R0402]  81.48 99.3 180 bottom
R195  -  [R0402]  81.48 101.54 180 bottom
R196  -  [R0402]  81.48 100.4 180 bottom
R197  -  [R0402]  172.97 101.23 0 top
R198  -  [R0402]  172.59 99.84 90 top
R199  -  [R0402]  157.1 26.18 90 top
R200  -  [R0402]  158.12 26.18 270 top
R201  -  [R0402]  131.91 25.28 180 bottom
R202  -  [R0402]  124.85 57.07 180 bottom
R203  -  [R0402]  128.63 57.06 180 top
R204  -  [R0402]  135.7 24.38 0 top
R205  -  [R0402]  131.91 24.39 0 bottom
R206  -  [R0402]  124.85 56.18 0 bottom
R207  -  [R0402]  128.63 56.17 0 top
R208  -  [R0402]  123.67 91.08 270 bottom
R209  -  [R0402]  125.97 95.41 180 top
R210  -  [R0402]  124.56 91.08 90 bottom
R211  -  [R0402]  125.97 94.52 0 top
R212  -  [R0402]  149.86 35.07 0 top
R221  -  [R0805]  155.32 13.48 90 bottom
R222  -  [R0805]  161.67 52.21 90 top
R223  -  [R0805]  167.64 85.61 0 top
R234  -  [R0805]  57.02 85.61 90 top
R235  -  [R0805]  136.02 13.6 90 bottom
R236  -  [R0805]  21.72 21.35 180 bottom
R238  -  [R0805]  28.4 66.08 180 bottom
R239  -  [R0805]  143 36.46 180 top
R240  -  [R0805]  52.07 24.02 0 bottom
R242  -  [R0805]  175.01 72.28 0 bottom
R243  -  [R0805]  142.88 75.96 0 top
R244  -  [R0805]  128.91 100.6 0 top
SHORT1  -  [SHORT10X30_M]  25.64 61.17 0 top
SHORT2  -  [SHORT10X30_M]  25.64 61.62 0 top
U1  -  [TSSOP24_P0-65W5-85H1-1_Z1]  110.62 105.31 0 top
U2  -  [MSOP10_P0-5W4-4_3X3]  94.91 101.56 0 top
U3  -  [SOIC8]  164.95 94.14 180 top
U4  -  [SC70-6XB]  143.18 21.22 180 bottom
U5  -  [SC70-6XB]  142.19 18.89 180 bottom
U6  -  [SC70-6XB]  136.14 50.69 180 bottom
U7  -  [SC70-6XB]  133.55 48.43 180 bottom
U8  -  [SC70-6XB]  139.09 94.15 270 bottom
U9  -  [SC70-6XB]  141.43 92.65 270 bottom
U10  -  [SC70-6XB]  180.95 79.9 0 bottom
U11  -  [SC70-6XB]  182.45 82.74 0 bottom
U12  -  [SC70-5XA]  146.56 33.29 180 top
U13  -  [TSSOP8_P0-65W3-7H1-1]  175.49 87.56 180 top
U14  -  [TSSOP16_P0-65W5-85H1-1XB]  78.87 107.71 180 top
U15  -  [VSSOP8]  143.99 26.51 180 bottom
U16  -  [VSSOP8]  135.36 56.05 180 bottom
U17  -  [VSSOP8]  133.81 94.45 270 bottom
U18  -  [VSSOP8]  182.07 73.75 180 bottom
U19  -  [VSSOP8]  117.65 31.99 0 bottom
U20  -  [TSOT8]  104.83 5.78 90 top
U21  -  [SC70-5XB]  32.51 110.12 180 top
U22  -  [SC70-5XB]  66.6 3.22 0 top
U23  -  [SC70-5XB]  112.65 2.17 0 bottom

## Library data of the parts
C1-C4 C18-C20 C65 C69 C72 C77-C84 C87 C89 PC101-PC103 PC106 = CAPP: part number: CAPP_-270UF,CAP-PLE00270-E0,POLCAP,20%,16V
C5-C8 C21 C22 C66 C70 C74 C88 C92 C117 C118 C120 C126 = CAP: part number: CAP_0805-10UF,CAP-85E00010-D0,X6S,10%,16V
C9-C12 = CAP: part number: CAP_0805-0.1UF,CAP-85G000D1-C0,X7R,5%,50V
C13-C15 C17 = CAP: part number: CAP_0603-1000PF,CAP-63G0D001-C0,X7R,5%,50V
C16 C23 C24 C26-C36 C61 C62 C67 C71 C75 C86 C91 C97-C104 C107 C109 C114 C115 C119 C121 C123 C127 PC28 PC33 PC835 PC851 PC1011 PC1835 PC1851 = CAP: part number: CAP_0402-0.1UF,CAP-42E000D1-D0,X7R,10%,16V
C25 C128-C152 C166-C168 C170-C172 C174-C176 C178 C191-C193 PC823 PC1823 = CAP: part number: CAP_0402-100PF,CAP-42GD0001-C0,NP0,5%,50V
C37 C38 PC842 PC1842 = CAP: part number: CAP_0402-2200PF,CAP-42GD0022-D0,X7R,10%,50V
C39-C42 C49-C52 = CAP: part number: CAP_0402-100PF,CAP-42GD0001-C0,EMPTY,5%,50V
C43 C44 C53 C54 C59 C60 PC825 PC1825 = CAP: part number: CAP_0402-0.1UF,CAP-42F000D1-D0,X7R,10%,25V
C45 C46 C55 C56 C63 C64 C68 C73 C76 C85 C90 C93-C96 C105 C111-C113 C122 C124 C125 PC819 PC1016 PC1021 PC1819 = CAP: part number: CAP_0402-1000PF,CAP-42G0D001-D0,X7R,10%,50V
C47 C48 C57 C58 = CAP: part number: CAP_0402-1UF,CAP-42C00001-D0,X7R,10%,6.3V
C106 = CAP: part number: CAP_0402-0.015UF,CAP-42E0D015-D0,X7R,10%,16V
C108 PC828 PC1024 PC1828 = CAP: part number: CAP_0603-0.1UF,CAP-63G000D1-D0,X7R,10%,50V
C110 PC820 PC1820 = CAP: part number: CAP_0402-1000PF,CAP-42G0D001-D0,EMPTY,10%,50V
C116 = CAP: part number: CAP_0402-0.1UF,CAP-42E000D1-D0,EMPTY,10%,16V
C153-C165 = CAP: part number: CAP_0402-33PF,CAP-42G0033P-C0,NP0,5%,50V
CON1 = HEADER1X3: part number: HEADER1X3_-HEADER1X3S,COH-003SM254-02,IO,,,
D1 D6 = LED_2P: part number: LED_2P_-LTST-C193KGKT-5A,LED-S1SG000V-00,IC,,
D2-D5 = BAT54_7_F: part number: BAT54_7_F_-BAT54-7-F,DOD-DSBAT547-00,IC,,,
D7-D10 = SCHOTTKY_BARRIER_RECTIFIER_3S: part number: SCHOTTKY_BARRIER_RECTIFIER_3S_-PDS1040-13,DOD-DSPDS104-00,IC,,
D11 PD1 = TVS_DIODE: part number: TVS_DIODE_-5.0SMDJ15A,DOD-LF50SMDJ-00,IC,,,
J1 J3 J4 = PWR2X12: part number: PWR2X12_-PWR2X12,COP-024D4D20-00,IO,,
J2 = PWR2X12: part number: PWR2X12_-RA_2NH_PWR2X12,COP-024D4D20-03,IO,,
J5-J8 = HEADER2X9Z: part number: HEADER2X9Z_-1NH_HEADER2X9,COH-018DM200-00,IO,,
J9 J10 = HEADER2X4Z: part number: HEADER2X4Z_-1NH_HEADER2X4,COH-008DM002-02,IO,,
J11 J16-J18 = PWR2X6_2PG: part number: PWR2X6_2PG_-2D2NH_PWR2X6,COP-012D0003-01,IO,,,
J12 = PWR2X4: part number: PWR2X4_-2NH_PWR2X4,COP-008D4D20-01,IO,,,
J13-J15 = PWR2X8_2PG: part number: PWR2X8_2PG_-2D2NH_PWR2X8,COP-016D0003-01,IO,,
J19 = PWR2X2_2PG: part number: PWR2X2_2PG_-2D2NH_PWR2X2,COP-004D0003-00,IO,,,
J20 = HEADER1X2: part number: HEADER1X2_-HEADER1X2,COH-002DM254-00,IO,,
J21 = HEADER2X3Z: part number: HEADER2X3Z_-1NH_HEADER2X3D,COH-006DM002-01,IO,,
L1-L26 L33 = BEAD: part number: BEAD_-47,BED-00470402-00,IC,25%,,
ME1 = DUMMY_SYMBOL_NO_PIN: part number: DUMMY_SYMBOL_NO_PIN_-ZT_LOG_6X16,MEDUMMY3,EMPTY,,
ME2 = DUMMY_SYMBOL_NO_PIN: part number: DUMMY_SYMBOL_NO_PIN_-LABEL20X4_SST21X5,MEDUMMY5,EMPTY,,
ME3 = DUMMY_SYMBOL_NO_PIN: part number: DUMMY_SYMBOL_NO_PIN_-LABEL_32X6_FULL,MEDUMMY7,EMPTY,,
MH1-MH5 = SCREW_NP_5VIA: part number: SCREW_NP_5VIA_-C10D4XC10D6.5_5V,TEMP_C10D4XC10D6.5_L5,EMPTY,,
MH6 MH7 = STANDOFF: part number: STANDOFF_-HOLE_C10D5-6B10_NPB_H11_STANDOFF,TSW-AM3L5P1P-01,IO,,
PC29-PC32 PC837 PC838 PC841 PC845 PC848 PC850 PC1834 PC1837 PC1838 PC1840 PC1841 PC1844 PC1845 PC1847 PC1848 PC1850 = CAP: part number: CAP_0805-22UF,CAP-85C00022-E0,X6S,20%,6.3V
PC34 PC109 = CAP: part number: CAP_0603-1UF,CAP-63E00001-D0,X6S,10%,16V
PC104 PC105 PC107 PC108 = CAP: part number: CAP_0805-22UF,CAP-85E00022-E0,X6S,20%,16V
PC822 PC1822 = CAP: part number: CAP_0603-2.2UF,CAP-63D002D2-D0,X7R,10%,10V
PC824 PC1017 PC1824 = CAP: part number: CAP_0603-1UF,CAP-63F00001-D0,X7R,10%,25V
PC827 PC830 PC849 PC1827 PC1830 PC1832 PC1833 PC1849 = CAP: part number: CAP_1206-22UF,CAP-C6F00022-E0,X6S,20%,25V
PC829 PC1829 = CAP: part number: CAP_0402-150PF,CAP-42G0150P-C0,NP0,5%,50V
PC831 PC1010 PC1012-PC1015 PC1023 PC1831 = CAP: part number: CAP_0402-0.01UF,CAP-42E00D01-D0,X7R,10%,16V
PC832 PC833 PC836 PC843 PC846 PC1836 PC1843 PC1846 = CAP: part number: CAP_1206-10UF,CAP-C6F00010-D0,EMPTY,10%,25V
PC834 PC840 PC844 PC847 = CAP: part number: CAP_0805-22UF,CAP-85C00022-E0,EMPTY,20%,6.3V
PC1018-PC1020 = CAP: part number: CAP_0402-0.1UF,CAP-42F000D1-D0,EMPTY,10%,25V
PC1022 = CAP: part number: CAP_0603-0.047UF,CAP-63G0D047-D0,X7R,10%,50V
PL26 = INDUCTOR: part number: INDUCTOR_-4.7UH,IND-C063T4R7-M0,IC,20%,5.5A,
PL28 PL128 = BEAD: part number: BEAD_-22,BED-00222012-00,IC,25%,,
PL126 = INDUCTOR: part number: INDUCTOR_-2.2UH,IND-C104T2R2-M0,IC,20%,12A,
PQ2 Q1 Q2 Q13-Q22 = 2N7002DW: part number: 2N7002DW_-2N7002KDW,MOS-2N7002DW-00,IC,,,
PQ3 Q5 = IRFH8202PBF: part number: IRFH8202PBF_-IRFH8202TRPBF,ICP-IRFH8202-00,IC,,,
PQ101-PQ108 = MOSFET_NCH_1D3S: part number: MOSFET_NCH_1D3S_-NTMFS4H01NT3G,MOS-NTMFS4H0-00,IC,,
PQ109 Q10 Q11 = NPN: part number: NPN_-MMBT3904LT1G,BJT-MMBT3904-00,IC,,,
PR22 PR704 PR1014 PR1041 PR1042 R1-R6 R12-R16 R52-R56 R65 R68-R74 R89-R92 R113-R116 R130 R131 R144 R145 R154 R155 R159-R162 R170 R172 R183 R184 R186 R187 R191-R196 = RES: part number: RES_0402-0,RES-42000000-C0,IC,5%,1A
PR23-PR25 PR1048 R157 = RES: part number: RES_0402-49.9K,RES-42049D9K-B0,IC,1%,1/16W
PR26 R21-R24 = RES: part number: RES_0603-2.2,RES-630002D2-C0,IC,5%,1/10W
PR27 PR1045 R156 R167 = RES: part number: RES_0402-1K,RES-4200001K-B0,IC,1%,1/16W
PR101-PR107 PR1039 PR1049 R49 = RES: part number: RES_0603-10,RES-63000010-B0,IC,1%,1/10W
PR108 PR1010 PR1012 PR1034 PR1035 PR1038 R26-R35 = RES: part number: RES_0402-100K,RES-4200100K-B0,IC,1%,1/16W
PR109 = RES: part number: RES_0402-6.19K,RES-4206D19K-B0,IC,1%,1/16W
PR702 R66 R67 R75 R76 = RES: part number: RES_0402-0,RES-42000000-C0,EMPTY,5%,1A
PR705 PR1705 PR1710 PR10152-PR10154 R7-R11 R17-R20 R46 R59 R60 R93-R100 R107-R109 R118 R120 R124 R153 R173 R199 = RES: part number: RES_0402-4.7K,RES-42004D7K-B0,IC,1%,1/16W
PR706 = RES: part number: RES_0402-39.2K,RES-42039D2K-B0,IC,1%,1/16W
PR707 PR708 PR719 PR1040 PR1707 PR1708 PR1719 R47 R50 = RES: part number: RES_0603-0,RES-63000000-C0,IC,5%,1A
PR710 = RES: part number: RES_0402-6.8K,RES-42006D8K-B0,IC,1%,1/16W
PR711 PR712 PR1711 PR1712 R132 R133 R146 R147 R164 = RES: part number: RES_0402-2.2K,RES-42002D2K-B0,IC,1%,1/16W
PR714 PR717 PR1037 PR1714 PR1717 R152 = RES: part number: RES_0402-12.4K,RES-42012D4K-B0,IC,1%,1/16W
PR716 PR1716 = RES: part number: RES_0402-120,RES-42000120-B0,IC,1%,1/16W
PR1011 = RES: part number: RES_0402-49.9K,RES-42049D9K-B0,EMPTY,1%,1/16W
PR1013 = RES: part number: RES_0402-7.87K,RES-4207D87K-B0,IC,1%,1/16W
PR1015-PR1020 PR1027-PR1032 R58 R139 R182 R201-R211 = RES: part number: RES_0402-10,RES-42000010-B0,IC,1%,1/16W
PR1033 = RES: part number: RES_0402-7.5K,RES-42007D5K-B0,IC,1%,1/16W
PR1036 = RES: part number: RES_0402-80.6K,RES-42080D6K-B0,IC,1%,1/16W
PR1043 PR1044 = RES: part number: RES_0402-33,RES-42000033-B0,IC,1%,1/16W
PR1046 PR1047 R61 R78 R80 R82 R84 R86 R88 R117 R123 R169 = RES: part number: RES_0402-100,RES-42000100-B0,IC,1%,1/16W
PR1050 = RES: part number: RES_0402-5.1K,RES-42005D1K-B0,IC,1%,1/16W
PR1706 = RES: part number: RES_0402-44.2K,RES-42044D2K-B0,IC,1%,1/16W
PSHORT5-PSHORT7 PSHORT15 PSHORT61 PSHORT71 = SHORT: part number: SHORT_-0805,,,,,
PU10 PU11 PU13-PU16 = RES_SHUNT_2P: part number: RES_SHUNT_2P_-0.0003,RES-PC0D0003-B0,IC,1%,3W
PU12 = ADM1278: part number: ADM1278_-ADM1278-2ACPZ-RL,ICP-ADM12782-00,IC
PU17-PU23 R189 = RES_SHUNT_2P: part number: RES_SHUNT_2P_-0.0005,RES-PC0D0005-B0,IC,1%,3W
PU33 = IR3897: part number: IR3897_-IR3897MTRPBF,ICP-IR3897MT-00,IC,,
PU113 = IR3899: part number: IR3899_-IR3899MTPRPBF,ICP-IR3899MT-00,IC,,
Q3 Q4 = 2N7002: part number: 2N7002_-2N7002,MOS-002N7002-00,IC,,,
R25 R126 R128 R136 R137 R140 R142 R150 R151 R163 R168 = RES: part number: RES_0402-10K,RES-4200010K-B0,IC,1%,1/16W
R36-R39 R62-R64 R188 = RES: part number: RES_0402-10K,RES-4200010K-B0,EMPTY,1%,1/16W
R40-R43 = RES: part number: RES_0603-680,RES-63000680-B0,IC,1%,1/10W
R44 R45 R174-R179 = RES: part number: RES_0402-220,RES-42000220-B0,IC,1%,1/16W
R48 = RES_SHUNT_2P: part number: RES_SHUNT_2P_-0.003,RES-PC00D003-B0,IC,1%,3W
R51 = RES: part number: RES_0402-49.9,RES-420049D9-B0,IC,1%,1/16W
R57 R221-R223 R234-R236 R238-R240 R242-R244 = RES: part number: RES_0805-49.9,RES-850049D9-B0,IC,1%,1/8W
R77 R79 R81 R83 R85 R87 R101-R104 R110-R112 R122 R185 R197 R212 = RES: part number: RES_0402-4.7K,RES-42004D7K-B0,EMPTY,1%,1/16W
R105 R106 = RES: part number: RES_0402-2.7K,RES-42002D7K-B0,IC,1%,1/16W
R119 R121 = RES: part number: RES_0402-100,RES-42000100-B0,EMPTY,1%,1/16W
R125 = RES: part number: RES_0603-10K,RES-6300010K-B0,EMPTY,1%,1/10W
R127 R129 R141 R143 = RES: part number: RES_0402-13.3K,RES-42013D3K-B0,IC,1%,1/16W
R134 R135 R148 R149 = RES: part number: RES_0402-20K,RES-4200020K-B0,IC,1%,1/16W
R138 = RES: part number: RES_0603-4.99K,RES-6304D99K-B0,EMPTY,1%,1/10W
R158 = RES: part number: RES_0402-18.7K,RES-42018D7K-B0,IC,1%,1/16W
R165 = RES: part number: RES_0402-1.43K,RES-4201D43K-B0,IC,1%,1/16W
R166 = RES: part number: RES_0402-4.99K,RES-4204D99K-F0,IC,0.1%,1/16W
R171 R200 = RES: part number: RES_0402-31.6K,RES-42031D6K-B0,IC,1%,1/16W
R180 = RES: part number: RES_0402-42.2K,RES-42042D2K-B0,IC,1%,1/16W
R181 = RES: part number: RES_0402-1.62K,RES-4201D62K-B0,IC,1%,1/16W
R198 = RES: part number: RES_0402-31.6K,RES-42031D6K-B0,EMPTY,1%,1/16W
SHORT1 SHORT2 = SHORT: part number: SHORT_-SHORT10X30_M,,,,,
U1 = PCA9555A: part number: PCA9555A_-PCA9555APW,ICC-PCA9555A-00,IC,,
U2 = EMC1413AAIZLTR: part number: EMC1413AAIZLTR_-EMC1413-A-AIZL-TR,ICC-EMC1413A-00,IC,,
U3 = AT24C64D: part number: AT24C64D_-AT24C64D-SSHM-T,ICM-AT24C64D-00,IC,,
U4-U11 = SN74LVC2G14: part number: SN74LVC2G14_-SN74LVC2G14DCKR,ICC-LVC2G14D-00,IC,,,
U12 = NC7SZ08P5X: part number: NC7SZ08P5X_-NC7SZ08P5X,ICC-NC7SZ08P-00,IC,,,
U13 = 74LVC2G08DP: part number: 74LVC2G08DP_-74LVC2G08DP,ICC-LVC2G08D-00,IC,,
U14 = PCA9546APW: part number: PCA9546APW_-PCA9546APW,ICC-PCA9546A-00,IC,,
U15-U18 = INA301: part number: INA301_-INA301,ICP-INA301A2-00,IC,,
U19 = LM393: part number: LM393_-LM393,ICP-LM393DGK-00,IC,,
U20 = ADM1172: part number: ADM1172_-ADM1172-2AUJZ-RL7,ICP-ADM11722-00,IC,,
U21-U23 = SN74LVC1G07: part number: SN74LVC1G07_-SN74LVC1G07DCKR,ICC-LVC1G07D-00,IC,,,

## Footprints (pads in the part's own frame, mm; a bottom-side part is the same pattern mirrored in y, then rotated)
B0402
  rect 0.457x0.508 smd: 1(-0.4,0) 2(0.4,0)
B2012
  rect 1.118x1.372 smd: 1(-0.95,0) 2(0.95,0)
C0402
  rect 0.457x0.508 smd: 1(-0.4,0) 2(0.4,0)
C0603
  rect 0.813x0.711 smd: 1(-0.737,0) 2(0.737,0)
C0805
  rect 1.118x1.372 smd: 1(-0.95,0) 2(0.95,0)
C1206
  rect 1.168x1.575 smd: 1(-1.473,0) 2(1.473,0)
D_SMCJ_6-85X5-9H2-62
  rect 2.413x3.302 smd: 1(3.3,0) 2(-3.3,0)
DFN5_P1-27_4-9X5-9_Z1
  rect 0.762x1.016 smd: 1(1.905,2.795) 2(0.635,2.795) 3(-0.635,2.795) 4(-1.905,2.795)
  custom 1.132x1.132 smd: 5_8(0,0)
EC_F80_H8
  oval 3.302x1.397 smd: 1(-2.464,0) 2(2.464,0)
GND_C10D4_6-5B10_OB5
  round 4.013 hole 4.013 unplated: (0,0)
  round 0.762 hole 0.559: 2(-3.5,0) 3(-2.475,2.475) 4(0,3.5) 5(2.475,2.475) 6(3.5,0)
HEADER1X2_P2-54H8-6
  rect 1.549x1.549 hole 1.041: 1(0,0)
  round 1.549 hole 1.041: 2(0,-2.54)
HEADER1X3S_P2-54H9-65XA
  rect 2.972x1.27 smd: 1(1.8,2.54) 2(-1.8,0) 3(1.8,-2.54)
HEADER2X3D1NH_P2W2H6-4
  round 1.016 hole 1.016 unplated: (3,1)
  rect 1.321x1.321 hole 0.914: 1(0,0)
  round 1.321 hole 0.914: 2(0,2) 3(2,0) 4(2,2) 5(4,0) 6(4,2)
HEADER2X4D1NH_P2W2H6-4
  round 1.016 hole 1.016 unplated: (5,1)
  rect 1.321x1.321 hole 0.914: 1(0,0)
  round 1.321 hole 0.914: 2(0,2) 3(2,0) 4(2,2) 5(4,0) 6(4,2) 7(6,0) 8(6,2)
HEADER2X9D1NH_P2W2H6-4
  round 1.016 hole 1.016 unplated: (15,1)
  rect 1.321x1.321 hole 0.914: 1(0,0)
  round 1.321 hole 0.914: 2(0,2) 3(2,0) 4(2,2) 5(4,0) 6(4,2) 7(6,0) 8(6,2) 9(8,0) 10(8,2) 11(10,0) 12(10,2) 13(12,0) 14(12,2) 15(14,0) 16(14,2) 17(16,0) 18(16,2)
HOLE_C10D5-6B10_NPB_H11_STANDOFF
  round 10.008 hole 5.613: 1(0,0)
IND_PCMB104TXA
  rect 4.115x4.115 smd: 1(-4.75,0) 2(4.75,0)
IND_PCMC063T
  rect 2.362x3.505 smd: 1(-3.025,0) 2(3.025,0)
LED0603
  rect 0.813x0.813 smd: A(-0.75,0) C(0.75,0)
LFCSP_WQ32_TH
  rect 0.914x0.279 smd: 1(-2.55,1.75) 8(-2.55,-1.75) 17(2.55,-1.75) 24(2.55,1.75)
  rect 1.016x0.279 smd: 2(-2.5,1.25) 3(-2.5,0.75) 4(-2.5,0.25) 5(-2.5,-0.25) 6(-2.5,-0.75) 7(-2.5,-1.25) 18(2.5,-1.25) 19(2.5,-0.75) 20(2.5,-0.25) 21(2.5,0.25) 22(2.5,0.75) 23(2.5,1.25)
  rect 0.279x0.914 smd: 9(-1.75,-2.55) 16(1.75,-2.55) 25(1.75,2.55) 32(-1.75,2.55)
  rect 0.279x1.016 smd: 10(-1.25,-2.5) 11(-0.75,-2.5) 12(-0.25,-2.5) 13(0.25,-2.5) 14(0.75,-2.5) 15(1.25,-2.5) 26(1.25,2.5) 27(0.75,2.5) 28(0.25,2.5) 29(-0.25,2.5) 30(-0.75,2.5) 31(-1.25,2.5)
  rect 3.454x3.454 smd: 33(0,0)
MSOP10_P0-5W4-4_3X3
  rect 1.422x0.279 smd: 1(-2.2,1) 2(-2.2,0.5) 3(-2.2,0) 4(-2.2,-0.5) 5(-2.2,-1) 6(2.2,-1) 7(2.2,-0.5) 8(2.2,0) 9(2.2,0.5) 10(2.2,1)
POWERDI5_5-37X3-96
  rect 1.397x1.422 smd: 1(-2.862,0.92) 2(-2.862,-0.92)
  rect 4.877x3.378 smd: 3(1.12,0)
PQFN17_IR3899
  rect 0.254x0.762 smd: 1(-1.5,-2.425) 2(-1,-2.425) 3(-0.5,-2.425) 4(0,-2.425) 5(0.5,-2.425) 6(1,-2.425) 7(1.5,-2.425)
  rect 0.762x0.254 smd: 8(1.925,-1.645) 9(1.925,-1.145) 10(1.925,-0.645) 14(-1.925,-0.645) 15(-1.925,-1.145) 16(-1.925,-1.645)
  custom 0.2x0.2 smd: 11(1.695,1.205)
  custom 0.405x0.405 smd: 12(0.285,1.395)
  custom 0.343x0.343 smd: 13(-1.615,1.205)
  rect 2.184x1.194 smd: 17(0,-1.145)
PWR2X2D2D2NH_P3W3H10-15
  round 1.092 hole 1.092 unplated: (-3.94,3) (-3.94,-6)
  rect 1.6x1.6 hole 1.092: 1(0,0)
  round 1.6 hole 1.092: 2(0,-3) 3(-3,0) 4(-3,-3)
  oval 3.531x1.219 hole 2.515x0.813: 5(-1.5,2.15) 6(-1.5,-5.15)
PWR2X4D2NH_P4-2W5-5H12-8
  round 3.048 hole 3.048 unplated: (-5.04,4.7) (-5.04,-17.3)
  rect 1.956x1.956 hole 1.448: 1(0,0)
  round 1.956 hole 1.448: 2(0,-4.2) 3(0,-8.4) 4(0,-12.6) 5(-5.5,0) 6(-5.5,-4.2) 7(-5.5,-8.4) 8(-5.5,-12.6)
PWR2X6D2D2NH_P3W3H10-15
  round 1.092 hole 1.092 unplated: (-3.94,3) (-3.94,-18)
  rect 1.6x1.6 hole 1.092: 1(0,0)
  round 1.6 hole 1.092: 2(0,-3) 3(0,-6) 4(0,-9) 5(0,-12) 6(0,-15) 7(-3,0) 8(-3,-3) 9(-3,-6) 10(-3,-9) 11(-3,-12) 12(-3,-15)
  oval 3.531x1.219 hole 2.515x0.813: 13(-1.5,2.15) 14(-1.5,-17.15)
PWR2X8D2D2NH_P3W3H10-15
  round 1.092 hole 1.092 unplated: (-3.94,3) (-3.94,-24)
  rect 1.6x1.6 hole 1.092: 1(0,0)
  round 1.6 hole 1.092: 2(0,-3) 3(0,-6) 4(0,-9) 5(0,-12) 6(0,-15) 7(0,-18) 8(0,-21) 9(-3,0) 10(-3,-3) 11(-3,-6) 12(-3,-9) 13(-3,-12) 14(-3,-15) 15(-3,-18) 16(-3,-21)
  oval 3.531x1.219 hole 2.515x0.813: 17(-1.5,2.15) 18(-1.5,-23.15)
PWR2X12D2NH_P4-2W5-5H10_RA
  round 3.073 hole 3.073 unplated: (7.3,0) (7.3,-46.2)
  rect 2.616x2.616 hole 1.854: 1(0,0)
  round 2.616 hole 1.854: 2(0,-4.2) 3(0,-8.4) 4(0,-12.6) 5(0,-16.8) 6(0,-21) 7(0,-25.2) 8(0,-29.4) 9(0,-33.6) 10(0,-37.8) 11(0,-42) 12(0,-46.2) 13(-5.5,0) 14(-5.5,-4.2) 15(-5.5,-8.4) 16(-5.5,-12.6) 17(-5.5,-16.8) 18(-5.5,-21) 19(-5.5,-25.2) 20(-5.5,-29.4) 21(-5.5,-33.6) 22(-5.5,-37.8) 23(-5.5,-42) 24(-5.5,-46.2)
PWR2X12D_P4-2W5-5H12-8
  rect 1.956x1.956 hole 1.448: 1(0,0)
  round 1.956 hole 1.448: 2(0,-4.2) 3(0,-8.4) 4(0,-12.6) 5(0,-16.8) 6(0,-21) 7(0,-25.2) 8(0,-29.4) 9(0,-33.6) 10(0,-37.8) 11(0,-42) 12(0,-46.2) 13(-5.5,0) 14(-5.5,-4.2) 15(-5.5,-8.4) 16(-5.5,-12.6) 17(-5.5,-16.8) 18(-5.5,-21) 19(-5.5,-25.2) 20(-5.5,-29.4) 21(-5.5,-33.6) 22(-5.5,-37.8) 23(-5.5,-42) 24(-5.5,-46.2)
R0402
  rect 0.457x0.508 smd: 1(-0.4,0) 2(0.4,0)
R0603
  rect 0.813x0.711 smd: 1(-0.737,0) 2(0.737,0)
R0805
  rect 1.118x1.372 smd: 1(-0.95,0) 2(0.95,0)
R2512_SMD126X146
  rect 3.2x3.708 smd: 1(-2.075,0) 2(2.075,0)
R2512XA_Z1
  rect 3.048x3.683 smd: 1(-2.159,0) 2(2.159,0)
SC70-5XA
  rect 0.508x0.406 smd: 1(-0.95,0.65) 2(-0.95,0) 3(-0.95,-0.65) 4(0.95,-0.65) 5(0.95,0.65)
SC70-5XB
  rect 0.914x0.406 smd: 1(-1.1,0.65) 2(-1.1,0) 3(-1.1,-0.65) 4(1.1,-0.65) 5(1.1,0.65)
SC70-6XB
  rect 0.864x0.356 smd: 1(-1.1,0.65) 2(-1.1,0) 3(-1.1,-0.65) 4(1.1,-0.65) 5(1.1,0) 6(1.1,0.65)
SHORT10X30_M
  rect 0.762x0.254 smd: 1(-0.191,0)
  rect 0.381x0.254 smd: 2(0.191,0)
SHORT0805
  custom 0.343x0.343 smd: 1(-0.94,0)
  rect 1.118x1.372 smd: 2(0.94,0)
SOIC8
  rect 1.727x0.559 smd: 1(-2.642,1.905) 2(-2.642,0.635) 3(-2.642,-0.635) 4(-2.642,-1.905) 5(2.642,-1.905) 6(2.642,-0.635) 7(2.642,0.635) 8(2.642,1.905)
SOT23
  rect 0.914x0.813 smd: 1(-1,0.95) 2(-1,-0.95) 3(1,0)
SOT23_GDS
  rect 1.422x1.016 smd: D(1.1,0) G(-1.1,0.95) S(-1.1,-0.95)
SOT363
  rect 0.61x0.432 smd: 1(-0.95,0.65) 2(-0.95,0) 3(-0.95,-0.65) 4(0.95,-0.65) 5(0.95,0) 6(0.95,0.65)
SOT1023
  rect 1.524x0.61 smd: 1(-3.412,1.905) 2(-3.412,0.635) 3(-3.412,-0.635) 4(-3.412,-1.905)
  custom 1.102x1.102 smd: 5(1.11,0)
TSOT8
  rect 1.321x0.432 smd: 1(-1.092,0.975) 2(-1.092,0.325) 3(-1.092,-0.325) 4(-1.092,-0.975) 5(1.092,-0.975) 6(1.092,-0.325) 7(1.092,0.325) 8(1.092,0.975)
TSSOP8_P0-65W3-7H1-1
  rect 1.321x0.432 smd: 1(-1.85,0.975) 2(-1.85,0.325) 3(-1.85,-0.325) 4(-1.85,-0.975) 5(1.85,-0.975) 6(1.85,-0.325) 7(1.85,0.325) 8(1.85,0.975)
TSSOP16_P0-65W5-85H1-1XB
  rect 1.372x0.61 smd: 1(-2.925,2.375) 8(-2.925,-2.375) 9(2.925,-2.375) 16(2.925,2.375)
  rect 1.372x0.406 smd: 2(-2.925,1.625) 3(-2.925,0.975) 4(-2.925,0.325) 5(-2.925,-0.325) 6(-2.925,-0.975) 7(-2.925,-1.625) 10(2.925,-1.625) 11(2.925,-0.975) 12(2.925,-0.325) 13(2.925,0.325) 14(2.925,0.975) 15(2.925,1.625)
TSSOP24_P0-65W5-85H1-1_Z1
  rect 1.372x0.61 smd: 1(-2.925,3.675) 12(-2.925,-3.675) 13(2.925,-3.675) 24(2.925,3.675)
  rect 1.372x0.406 smd: 2(-2.925,2.925) 3(-2.925,2.275) 4(-2.925,1.625) 5(-2.925,0.975) 6(-2.925,0.325) 7(-2.925,-0.325) 8(-2.925,-0.975) 9(-2.925,-1.625) 10(-2.925,-2.275) 11(-2.925,-2.925) 14(2.925,-2.925) 15(2.925,-2.275) 16(2.925,-1.625) 17(2.925,-0.975) 18(2.925,-0.325) 19(2.925,0.325) 20(2.925,0.975) 21(2.925,1.625) 22(2.925,2.275) 23(2.925,2.925)
unnamed
  round 0.991 smd: 1(0,0)
VSSOP8
  rect 1.448x0.432 smd: 1(-2.2,0.975) 2(-2.2,0.325) 3(-2.2,-0.325) 4(-2.2,-0.975) 5(2.2,-0.975) 6(2.2,-0.325) 7(2.2,0.325) 8(2.2,0.975)

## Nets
